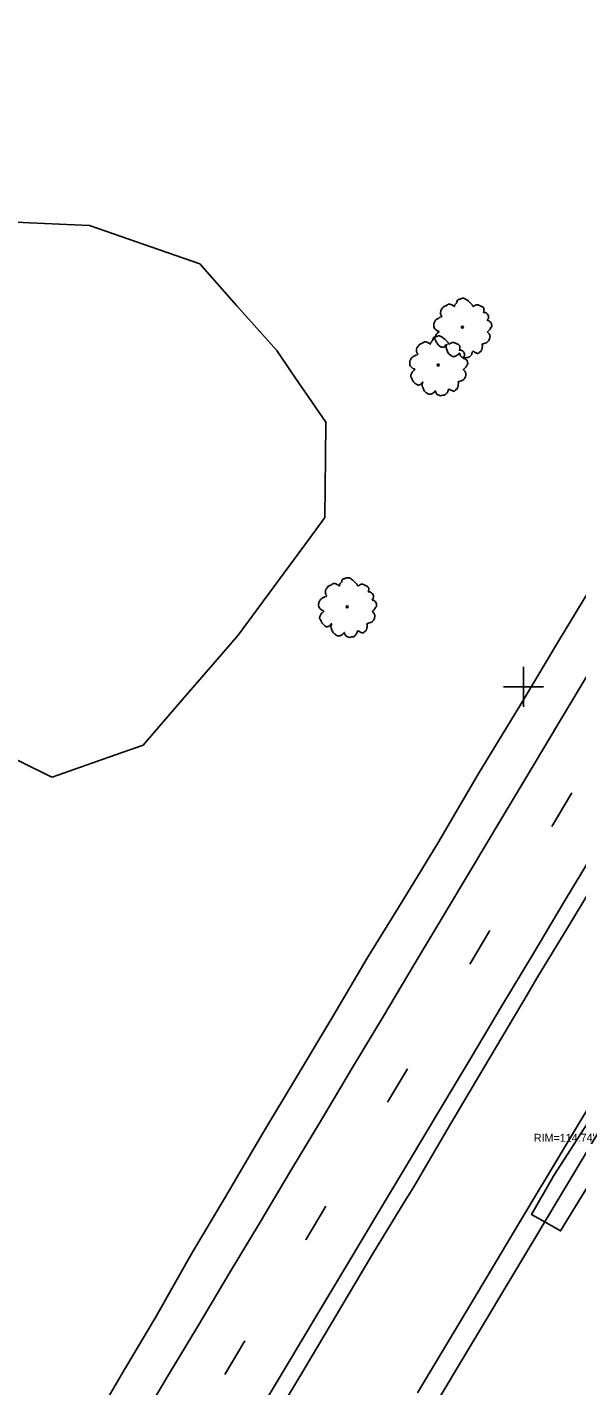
# Model space of a CAD drawing. Extents: x 2132221 to 2141942, y 535736 to 547298.
# Drawn here: x 2138327.6 to 2138464.8, y 541243.7 to 541583.2 of the extents above; entities that cross this region are included whole.
import ezdxf

# ---------------------------------------------------------------- set-up
doc = ezdxf.new("R2010")
doc.units = 0
for name, color, linetype in [('RD_EX_Conc', 7, 'Continuous'), ('RD_EX_DR_Inlet_txCode', 7, 'Continuous'), ('RD_EX_GuardRail', 7, 'Continuous'), ('RD_EX_Misc', 7, 'Continuous'), ('RD_EX_Road', 7, 'Continuous'), ('RD_EX_VEG', 7, 'Continuous'), ('RD_HC_Cl', 7, 'Continuous')]:
    doc.layers.add(name, color=color, linetype=linetype)

msp = doc.modelspace()

# ---------------------------------------------------------------- linework, layer by layer
at = {"layer": 'RD_EX_Conc'}
msp.add_lwpolyline([(2138476.09, 541307.1), (2138466.79, 541292.34), (2138460.77, 541282.35), (2138457.07, 541284.5), (2138453.47, 541286.5), (2138459.05, 541296.22), (2138469.23, 541311.98), (2138472.75, 541309.72)], close=True, dxfattribs=at)
at = {"layer": 'RD_EX_GuardRail'}
msp.add_lwpolyline([(2138636.97, 541596.05), (2138620.77, 541569.14), (2138611.98, 541554.42), (2138596.67, 541528.85), (2138582.3, 541504.88), (2138567.26, 541479.78), (2138552.31, 541454.62), (2138539.03, 541432.48), (2138522.9, 541405.55), (2138505.58, 541376.64), (2138486.91, 541345.38), (2138471.63, 541319.73), (2138451.06, 541285.46), (2138439.29, 541265.65), (2138425.02, 541241.91)], dxfattribs=at)
at = {"layer": 'RD_EX_Misc'}
for p, q in [((2138451.49, 541413.36), (2138451.49, 541423.36)), ((2138446.49, 541418.36), (2138456.49, 541418.36)), ((2138458.55, 541383.45), (2138463.55, 541391.84)), ((2138438.12, 541349.04), (2138443.12, 541357.43)), ((2138417.55, 541314.51), (2138422.54, 541322.89)), ((2138397.17, 541280.14), (2138402.17, 541288.53)), ((2138376.96, 541246.49), (2138381.95, 541254.88))]:
    msp.add_line(p, q, dxfattribs=at)
for points in [[(2138354.94, 541233.08), (2138362.64, 541245.96), (2138370.34, 541258.83), (2138378.04, 541271.7), (2138385.74, 541284.58), (2138393.44, 541297.45), (2138401.13, 541310.32), (2138408.83, 541323.2), (2138416.53, 541336.07), (2138424.23, 541348.95), (2138431.93, 541361.82), (2138438, 541371.98), (2138445.7, 541384.85), (2138453.4, 541397.72), (2138461.1, 541410.6), (2138468.79, 541423.47)], [(2138384.51, 541235.6), (2138392.22, 541248.47), (2138399.92, 541261.34), (2138407.62, 541274.22), (2138415.32, 541287.09), (2138423.02, 541299.96), (2138430.72, 541312.83), (2138438.42, 541325.71), (2138446.12, 541338.58), (2138453.82, 541351.45), (2138461.53, 541364.32), (2138469.23, 541377.19)]]:
    msp.add_lwpolyline(points, dxfattribs=at)
at = {"layer": 'RD_EX_Road'}
for points in [[(2138346.62, 541238.77), (2138351.88, 541247.72), (2138359.61, 541260.77), (2138368.64, 541276.63), (2138376.87, 541290.5), (2138386.45, 541306.82), (2138395.1, 541321.18), (2138403.89, 541335.94), (2138412.46, 541350.55), (2138421.36, 541364.9), (2138430.09, 541379.27), (2138440.23, 541396.53), (2138451.54, 541415.09), (2138460.25, 541429.74), (2138472.29, 541449.62), (2138482.81, 541467.18), (2138492.39, 541483.49), (2138505.21, 541504.79), (2138514.78, 541521.06), (2138527.82, 541542.56), (2138538.94, 541561.17), (2138548.1, 541576.55), (2138563.93, 541602.75)], [(2138391.2, 541238.48), (2138397.19, 541248.45), (2138404.83, 541261.36), (2138412.46, 541274.27), (2138413.83, 541276.59), (2138421.67, 541289.38), (2138424.13, 541293.39), (2138431.7, 541306.34), (2138435.26, 541312.44), (2138442.92, 541325.33), (2138444.78, 541328.47), (2138452.41, 541341.38), (2138454.85, 541345.51), (2138462.62, 541358.34), (2138467.81, 541366.9)]]:
    msp.add_lwpolyline(points, dxfattribs=at)
at = {"layer": 'RD_EX_VEG'}
msp.add_lwpolyline([(2138319.66, 541402.67), (2138333.13, 541396.06), (2138333.82, 541395.72), (2138347.96, 541400.72), (2138356.52, 541403.74), (2138366.33, 541415.09), (2138376.13, 541426.44), (2138380.29, 541431.26), (2138389.19, 541443.34), (2138398.08, 541455.42), (2138401.93, 541460.66), (2138402.1, 541475.66), (2138402.2, 541484.44), (2138393.71, 541496.81), (2138389.91, 541502.34), (2138379.95, 541513.56), (2138370.68, 541523.99), (2138356.52, 541528.94), (2138343.17, 541533.61), (2138328.18, 541534.3), (2138319.93, 541534.68)], dxfattribs=at)
for centre, radius in [((2138436.24, 541508.17), 0.25), ((2138436.22, 541508.17), 0.0001), ((2138430.23, 541498.74), 0.25), ((2138430.21, 541498.74), 0.0001), ((2138407.49, 541438.34), 0.25), ((2138407.47, 541438.34), 0.0001)]:
    msp.add_circle(centre, radius, dxfattribs=at)
for points in [[(2138441.6, 541512.93), (2138441.41, 541513.17), (2138441.12, 541513.34), (2138440.88, 541513.46), (2138440.67, 541513.57), (2138440.44, 541513.67), (2138440.11, 541513.77), (2138439.81, 541513.8), (2138439.54, 541513.73), (2138439.35, 541513.61), (2138439.11, 541513.46), (2138438.98, 541513.34), (2138438.88, 541513.42), (2138438.79, 541513.54), (2138438.68, 541513.78), (2138438.51, 541513.96), (2138438.34, 541514.15), (2138438.09, 541514.39), (2138437.85, 541514.64), (2138437.63, 541514.81), (2138437.37, 541515.02), (2138437.02, 541515.21), (2138436.69, 541515.38), (2138436.31, 541515.43), (2138435.79, 541515.29), (2138435.45, 541515.15), (2138435.16, 541515.09), (2138434.93, 541514.67), (2138434.79, 541514.31), (2138434.66, 541514.15), (2138434.4, 541513.81), (2138434.3, 541513.59), (2138434.24, 541513.36), (2138434.17, 541513.4), (2138433.88, 541513.64), (2138433.61, 541513.79), (2138433.15, 541513.95), (2138432.83, 541513.96), (2138432.53, 541513.82), (2138432.25, 541513.6), (2138432.04, 541513.54), (2138431.79, 541513.41), (2138431.71, 541513.37), (2138431.44, 541513.19), (2138431.18, 541512.81), (2138430.94, 541512.56), (2138430.86, 541512.31), (2138430.83, 541512.08), (2138430.76, 541511.79), (2138430.87, 541511.34), (2138431.02, 541511.03), (2138431.13, 541510.87), (2138430.65, 541510.66), (2138430.36, 541510.46), (2138429.98, 541510.28), (2138429.92, 541510.23), (2138429.54, 541509.94), (2138429.4, 541509.61), (2138429.18, 541509.3), (2138429.13, 541509.02), (2138429.1, 541508.62), (2138429.15, 541508.23), (2138429.4, 541507.77), (2138429.69, 541507.5), (2138430.2, 541507.19), (2138430.43, 541507.06), (2138430.28, 541506.96), (2138430.02, 541506.69), (2138429.71, 541506.4), (2138429.58, 541506.07), (2138429.44, 541505.81), (2138429.36, 541505.53), (2138429.41, 541505.14), (2138429.63, 541504.79), (2138429.81, 541504.38), (2138430.06, 541504), (2138430.38, 541503.61), (2138430.89, 541503.27), (2138431.17, 541503.16), (2138431.37, 541503.2), (2138431.78, 541503.31), (2138431.91, 541503.5), (2138432.37, 541503.89), (2138432.31, 541503.69), (2138432.17, 541503.33), (2138432.29, 541502.76), (2138432.43, 541502.34), (2138432.64, 541501.89), (2138432.79, 541501.62), (2138433.17, 541501.32), (2138433.47, 541501.1), (2138433.82, 541500.91), (2138434.23, 541500.87), (2138434.55, 541500.93), (2138434.78, 541501.08), (2138435.11, 541501.28), (2138435.27, 541501.36)], [(2138435.27, 541501.36), (2138435.35, 541501.54), (2138435.5, 541501.74), (2138435.53, 541501.67), (2138435.61, 541501.51), (2138435.71, 541501.22), (2138435.8, 541501), (2138436.04, 541500.78), (2138436.3, 541500.65), (2138436.81, 541500.5), (2138437.35, 541500.62), (2138437.83, 541500.69), (2138438.12, 541500.86), (2138438.25, 541501.05), (2138438.6, 541501.4), (2138438.65, 541501.72), (2138438.7, 541501.84), (2138438.93, 541502.18), (2138439.02, 541502.16), (2138439.24, 541501.99), (2138439.59, 541501.8), (2138439.86, 541501.69), (2138440.15, 541501.64), (2138440.36, 541501.74), (2138440.64, 541502.03), (2138440.97, 541502.26), (2138441.03, 541502.42), (2138441.07, 541502.59), (2138441.17, 541502.78), (2138441.17, 541502.99), (2138441.22, 541503.17), (2138441.22, 541503.31), (2138441.25, 541503.5), (2138441.22, 541503.72), (2138441.16, 541503.86), (2138441.23, 541504), (2138441.48, 541504.03), (2138441.59, 541504.06), (2138441.77, 541504.19), (2138442.18, 541504.26), (2138442.51, 541504.5), (2138442.79, 541504.82), (2138442.96, 541505.04), (2138443.06, 541505.34), (2138443.1, 541505.66), (2138443.15, 541505.87), (2138443.12, 541506.08), (2138442.99, 541506.4), (2138442.86, 541506.62), (2138442.62, 541506.88), (2138442.53, 541507.06), (2138442.58, 541507.08), (2138442.69, 541507.18), (2138442.89, 541507.36), (2138443.17, 541507.72), (2138443.44, 541508.17), (2138443.46, 541508.19), (2138443.57, 541508.43), (2138443.57, 541508.73), (2138443.52, 541508.93), (2138443.48, 541509.16), (2138443.33, 541509.36), (2138443.12, 541509.58), (2138442.9, 541509.75), (2138442.69, 541509.83), (2138442.48, 541509.87), (2138442.54, 541510.03), (2138442.69, 541510.31), (2138442.77, 541510.44), (2138442.8, 541510.67), (2138442.79, 541510.97), (2138442.58, 541511.39), (2138442.1, 541511.8), (2138441.75, 541511.88), (2138441.52, 541511.88), (2138441.58, 541512), (2138441.59, 541512.28), (2138441.65, 541512.47), (2138441.62, 541512.68), (2138441.6, 541512.86), (2138441.57, 541512.97)], [(2138435.59, 541503.5), (2138435.41, 541503.74), (2138435.11, 541503.91), (2138434.87, 541504.03), (2138434.66, 541504.14), (2138434.44, 541504.24), (2138434.11, 541504.34), (2138433.81, 541504.37), (2138433.54, 541504.3), (2138433.34, 541504.18), (2138433.1, 541504.03), (2138432.97, 541503.91), (2138432.87, 541503.99), (2138432.79, 541504.11), (2138432.67, 541504.35), (2138432.5, 541504.53), (2138432.34, 541504.72), (2138432.08, 541504.96), (2138431.84, 541505.21), (2138431.62, 541505.38), (2138431.36, 541505.59), (2138431.02, 541505.78), (2138430.69, 541505.95), (2138430.3, 541506), (2138429.78, 541505.86), (2138429.44, 541505.72), (2138429.16, 541505.66), (2138428.93, 541505.25), (2138428.79, 541504.88), (2138428.66, 541504.73), (2138428.4, 541504.38), (2138428.3, 541504.16), (2138428.24, 541503.93), (2138428.17, 541503.97), (2138427.88, 541504.21), (2138427.6, 541504.36), (2138427.15, 541504.52), (2138426.83, 541504.54), (2138426.52, 541504.39), (2138426.25, 541504.17), (2138426.03, 541504.11), (2138425.78, 541503.98), (2138425.71, 541503.94), (2138425.43, 541503.76), (2138425.17, 541503.38), (2138424.93, 541503.13), (2138424.85, 541502.88), (2138424.82, 541502.65), (2138424.76, 541502.36), (2138424.86, 541501.91), (2138425.01, 541501.6), (2138425.13, 541501.44), (2138424.64, 541501.23), (2138424.35, 541501.03), (2138423.97, 541500.85), (2138423.92, 541500.8), (2138423.53, 541500.51), (2138423.4, 541500.18), (2138423.17, 541499.87), (2138423.12, 541499.59), (2138423.09, 541499.19), (2138423.14, 541498.8), (2138423.39, 541498.34), (2138423.68, 541498.07), (2138424.2, 541497.76), (2138424.42, 541497.63), (2138424.28, 541497.53), (2138424.02, 541497.26), (2138423.71, 541496.97), (2138423.57, 541496.64), (2138423.43, 541496.38), (2138423.35, 541496.1), (2138423.41, 541495.71), (2138423.62, 541495.36), (2138423.8, 541494.95), (2138424.05, 541494.57), (2138424.37, 541494.18), (2138424.89, 541493.84), (2138425.16, 541493.73), (2138425.36, 541493.77), (2138425.77, 541493.88), (2138425.9, 541494.07), (2138426.36, 541494.46), (2138426.3, 541494.26), (2138426.16, 541493.9), (2138426.28, 541493.33), (2138426.42, 541492.92), (2138426.63, 541492.46), (2138426.78, 541492.19), (2138427.16, 541491.89), (2138427.47, 541491.67), (2138427.81, 541491.48), (2138428.22, 541491.44), (2138428.54, 541491.5), (2138428.78, 541491.65), (2138429.1, 541491.85), (2138429.26, 541491.93)], [(2138429.26, 541491.93), (2138429.34, 541492.11), (2138429.49, 541492.31), (2138429.52, 541492.24), (2138429.61, 541492.08), (2138429.7, 541491.79), (2138429.8, 541491.57), (2138430.04, 541491.35), (2138430.3, 541491.22), (2138430.8, 541491.07), (2138431.34, 541491.19), (2138431.82, 541491.26), (2138432.11, 541491.43), (2138432.24, 541491.62), (2138432.59, 541491.97), (2138432.64, 541492.29), (2138432.7, 541492.41), (2138432.92, 541492.75), (2138433.01, 541492.73), (2138433.23, 541492.57), (2138433.58, 541492.37), (2138433.86, 541492.26), (2138434.14, 541492.21), (2138434.36, 541492.31), (2138434.63, 541492.6), (2138434.96, 541492.83), (2138435.02, 541492.99), (2138435.06, 541493.16), (2138435.16, 541493.35), (2138435.17, 541493.56), (2138435.21, 541493.74), (2138435.22, 541493.88), (2138435.24, 541494.07), (2138435.21, 541494.29), (2138435.15, 541494.43), (2138435.23, 541494.57), (2138435.48, 541494.6), (2138435.58, 541494.63), (2138435.76, 541494.76), (2138436.17, 541494.83), (2138436.5, 541495.07), (2138436.78, 541495.39), (2138436.95, 541495.61), (2138437.05, 541495.91), (2138437.1, 541496.23), (2138437.14, 541496.44), (2138437.12, 541496.65), (2138436.99, 541496.97), (2138436.85, 541497.19), (2138436.62, 541497.45), (2138436.52, 541497.63), (2138436.57, 541497.65), (2138436.68, 541497.75), (2138436.89, 541497.93), (2138437.17, 541498.29), (2138437.43, 541498.74), (2138437.45, 541498.76), (2138437.57, 541499), (2138437.56, 541499.3), (2138437.52, 541499.5), (2138437.47, 541499.73), (2138437.32, 541499.93), (2138437.12, 541500.15), (2138436.89, 541500.32), (2138436.69, 541500.4), (2138436.48, 541500.44), (2138436.53, 541500.6), (2138436.69, 541500.88), (2138436.76, 541501.02), (2138436.79, 541501.24), (2138436.79, 541501.55), (2138436.57, 541501.96), (2138436.09, 541502.37), (2138435.74, 541502.45), (2138435.51, 541502.45), (2138435.57, 541502.57), (2138435.58, 541502.85), (2138435.64, 541503.04), (2138435.62, 541503.26), (2138435.59, 541503.43), (2138435.56, 541503.54)], [(2138412.85, 541443.1), (2138412.67, 541443.34), (2138412.37, 541443.51), (2138412.13, 541443.62), (2138411.92, 541443.74), (2138411.7, 541443.84), (2138411.36, 541443.94), (2138411.07, 541443.97), (2138410.8, 541443.89), (2138410.6, 541443.77), (2138410.36, 541443.62), (2138410.23, 541443.51), (2138410.13, 541443.58), (2138410.05, 541443.71), (2138409.93, 541443.94), (2138409.76, 541444.13), (2138409.59, 541444.31), (2138409.34, 541444.55), (2138409.1, 541444.81), (2138408.88, 541444.98), (2138408.62, 541445.18), (2138408.28, 541445.37), (2138407.95, 541445.54), (2138407.56, 541445.6), (2138407.04, 541445.46), (2138406.7, 541445.31), (2138406.41, 541445.25), (2138406.18, 541444.84), (2138406.05, 541444.47), (2138405.92, 541444.32), (2138405.65, 541443.98), (2138405.56, 541443.75), (2138405.49, 541443.52), (2138405.43, 541443.56), (2138405.13, 541443.8), (2138404.86, 541443.96), (2138404.4, 541444.12), (2138404.09, 541444.13), (2138403.78, 541443.98), (2138403.51, 541443.76), (2138403.29, 541443.7), (2138403.04, 541443.57), (2138402.97, 541443.54), (2138402.69, 541443.36), (2138402.43, 541442.98), (2138402.19, 541442.72), (2138402.11, 541442.48), (2138402.08, 541442.25), (2138402.02, 541441.95), (2138402.12, 541441.5), (2138402.27, 541441.2), (2138402.39, 541441.03), (2138401.9, 541440.82), (2138401.61, 541440.62), (2138401.23, 541440.44), (2138401.17, 541440.39), (2138400.79, 541440.11), (2138400.65, 541439.78), (2138400.43, 541439.47), (2138400.38, 541439.19), (2138400.35, 541438.78), (2138400.4, 541438.39), (2138400.65, 541437.94), (2138400.94, 541437.66), (2138401.46, 541437.36), (2138401.68, 541437.22), (2138401.54, 541437.12), (2138401.28, 541436.85), (2138400.96, 541436.56), (2138400.83, 541436.23), (2138400.69, 541435.97), (2138400.61, 541435.69), (2138400.67, 541435.3), (2138400.88, 541434.96), (2138401.06, 541434.54), (2138401.31, 541434.16), (2138401.63, 541433.78), (2138402.15, 541433.44), (2138402.42, 541433.32), (2138402.62, 541433.37), (2138403.03, 541433.47), (2138403.16, 541433.66), (2138403.62, 541434.05), (2138403.56, 541433.86), (2138403.42, 541433.49), (2138403.54, 541432.92), (2138403.68, 541432.51), (2138403.89, 541432.06), (2138404.04, 541431.79), (2138404.42, 541431.49), (2138404.73, 541431.26), (2138405.07, 541431.07), (2138405.48, 541431.04), (2138405.8, 541431.1), (2138406.03, 541431.25), (2138406.36, 541431.44), (2138406.52, 541431.53)], [(2138406.52, 541431.53), (2138406.6, 541431.7), (2138406.75, 541431.91), (2138406.78, 541431.83), (2138406.87, 541431.67), (2138406.96, 541431.38), (2138407.06, 541431.17), (2138407.3, 541430.95), (2138407.56, 541430.81), (2138408.06, 541430.67), (2138408.6, 541430.79), (2138409.08, 541430.86), (2138409.37, 541431.02), (2138409.5, 541431.21), (2138409.85, 541431.57), (2138409.9, 541431.88), (2138409.96, 541432), (2138410.18, 541432.35), (2138410.27, 541432.33), (2138410.49, 541432.16), (2138410.84, 541431.97), (2138411.12, 541431.85), (2138411.4, 541431.8), (2138411.61, 541431.9), (2138411.89, 541432.19), (2138412.22, 541432.42), (2138412.28, 541432.58), (2138412.32, 541432.76), (2138412.42, 541432.95), (2138412.43, 541433.16), (2138412.47, 541433.33), (2138412.47, 541433.48), (2138412.5, 541433.67), (2138412.47, 541433.88), (2138412.41, 541434.03), (2138412.49, 541434.16), (2138412.73, 541434.19), (2138412.84, 541434.22), (2138413.02, 541434.35), (2138413.43, 541434.43), (2138413.76, 541434.66), (2138414.04, 541434.99), (2138414.21, 541435.21), (2138414.31, 541435.5), (2138414.36, 541435.82), (2138414.4, 541436.03), (2138414.37, 541436.24), (2138414.25, 541436.57), (2138414.11, 541436.79), (2138413.88, 541437.04), (2138413.78, 541437.22), (2138413.83, 541437.24), (2138413.94, 541437.34), (2138414.14, 541437.53), (2138414.42, 541437.89), (2138414.69, 541438.34), (2138414.71, 541438.35), (2138414.82, 541438.6), (2138414.82, 541438.9), (2138414.77, 541439.09), (2138414.73, 541439.32), (2138414.58, 541439.53), (2138414.38, 541439.75), (2138414.15, 541439.91), (2138413.94, 541439.99), (2138413.73, 541440.04), (2138413.79, 541440.19), (2138413.95, 541440.47), (2138414.02, 541440.61), (2138414.05, 541440.84), (2138414.04, 541441.14), (2138413.83, 541441.55), (2138413.35, 541441.96), (2138413, 541442.05), (2138412.77, 541442.04), (2138412.83, 541442.16), (2138412.84, 541442.44), (2138412.9, 541442.64), (2138412.88, 541442.85), (2138412.85, 541443.03), (2138412.82, 541443.13)]]:
    msp.add_spline(points, degree=3, dxfattribs=at)
at = {"layer": 'RD_HC_Cl'}
msp.add_line((2139719.79, 543396.28), (2136851.48, 538600.7), dxfattribs=at)
msp.add_arc((2137944.04, 542541.74), 972.38, 220.32405, 325.12405, dxfattribs=at)

# ---------------------------------------------------------------- texts
at = {"layer": 'RD_EX_DR_Inlet_txCode'}
msp.add_text("RIM=114.74'", height=2, dxfattribs=at).set_placement((2138454.1, 541304.63))

doc.saveas('drawing.dxf')
